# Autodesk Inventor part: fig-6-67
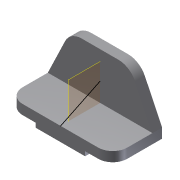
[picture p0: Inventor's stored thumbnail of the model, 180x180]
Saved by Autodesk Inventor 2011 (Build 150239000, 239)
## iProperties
Shininess: 77.0
Length Units: 11269
Angle Units: 11279
Time Units: 11290
Mass Units: 11283
Length Display Precision: 3
Angle Display Precision: 2
Created: 2001-12
Part Number: fig-6-67
Document SubType Name: Modeling
Designer: Renu Muthoo
Density: 1 g/cm^3
Density: 0.0
Volumn: 0.0
Area: 0.0
PropertySet Name: Model Information
Control State: 0
Master: False
Checked Out: False
Author: Renu Muthoo
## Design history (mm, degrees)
node "Sketch1"
sketch "Sketch2"
  geometry: L1 (-67.219, 19.116)-(148.781, 19.116); L2 (148.781, 19.116)-(148.781, -0.884); L3 (-67.219, -0.884)-(-67.219, 19.116); L4 (-10.219, -0.884)-(-10.219, -9.884); L5 (-10.219, -9.884)-(91.781, -9.884); L6 (91.781, -9.884)-(91.781, -0.884); L7 (148.781, -0.884)-(91.781, -0.884); L8 (-10.219, -0.884)-(-67.219, -0.884)
  constraints: 16 end point, 5 parallel, 4 perpendicular, 2 equal length, 1 horizontal
  dimensions: "d0" = 102 distance of L4.end L5.end; "d1" = 57 distance of L4.start L3.start; "d2" = 29 distance between parallel lines of L1 L5; "d3" = 20 distance of L1.end L2.end
extrude "Extrusion1" new body sketch "Sketch2" distance "d4" = 102; taper "d5" = 0 deg
sketch "Sketch3"
  geometry: L1 (67.219, -19.116)-(-148.781, -19.116) reference; L2 (67.219, -19.116)-(31.475, -93.564); L3 (-2.781, -115.116)-(-78.781, -115.116); L4 (-113.038, -93.564)-(-148.781, -19.116); A1 r 38 centre (-2.781, -77.116) between (-2.781, -115.116) and (31.475, -93.564); A2 r 38 centre (-78.781, -77.116) between (-113.038, -93.564) and (-78.781, -115.116)
  constraints: 6 end point, 4 point on circle, 4 tangent, 2 centre point, 1 equal length, 1 equal radius, 1 parallel
  dimensions: "d6" = 96 distance between parallel lines of L3 L1; "d7" = 38 radius of A1; "d8" = 76 distance of A2.centre A1.centre
extrude "Extrusion2" join sketch "Sketch3" distance "d9" = 20; taper "d10" = 0 deg
fillet "Fillet1" dims "d11" = 30
workplane "Work Plane1"
sketch "Sketch7"
  geometry: L1 (0, -82)-(-39.557, 0)
  constraints: 2 end point
body "Solid1"
other parameters: "d12" = -108
